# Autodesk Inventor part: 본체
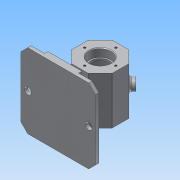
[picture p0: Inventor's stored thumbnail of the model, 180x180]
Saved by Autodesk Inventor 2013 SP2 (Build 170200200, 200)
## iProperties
Created: 2018-06
Part Number: 본체
Material: 알루미늄 6061
Document SubType Name: Modeling
Designer: Administrator
Density: 2.71 g/cm^3
Mass: 554.05 g
Surface Area: 601.88 cm^2
Volume: 204.446 cm^3
Author: Administrator
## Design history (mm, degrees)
sketch "스케치1"
  geometry: L1 (-55, -57)-(55, -57); L2 (55, -57)-(55, -62); L3 (55, -62)-(-55, -62); L4 (-55, -62)-(-55, -57); L5 (12.426, 30)-(30, 12.426); L6 (30, 12.426)-(30, -12.426); L7 (30, -12.426)-(12.426, -30); L8 (12.426, -30)-(-12.426, -30); L9 (-12.426, -30)-(-30, -12.426); L10 (-30, -12.426)-(-30, 12.426); L11 (-30, 12.426)-(-12.426, 30); L12 (-12.426, 30)-(12.426, 30); L13 (0, 0)-(-12.426, 30); L14 (0, 0)-(12.426, 30); L15 (-25, -57)-(25, -57); L16 (25, -57)-(25, -52); L17 (25, -52)-(-25, -52); L18 (-25, -52)-(-25, -57); C1 r 30 at (0, 0); 4 further points
  constraints: 36 end point, 4 parallel, 3 midpoint, 2 horizontal, 2 perpendicular, 2 vertical alignment, 1 centre point, 1 coincident, 1 horizontal alignment, 1 point on line, 1 tangent, 17 other
  dimensions: "d14" = 60 diameter of C1; "d16" = 110 distance of L2.end L3.end; "d17" = 5 distance of L3.end L1.start; "d18" = 62 distance from line of point (0, 0) L3; "d20" = 60 distance between parallel lines of L6 L10; "d21" = 30 vertical distance of L13.start L11.end; "d24" = 5 distance of L17.end L15.start; "d25" = 50 distance of L16.end L17.end
extrude "돌출1" new body sketch "스케치1" stored distance "d22" = 70; taper "d23" = 0 deg
extrude "돌출2" join sketch "스케치1" stored distance "d26" = 110; taper "d27" = 0 deg
extrude "돌출3" join sketch "스케치1" stored distance "d28" = 110; taper "d29" = 0 deg
sketch "스케치2"
  geometry: L1 (0, 110)-(50, 110) reference; L2 (20, 74)-(20, 36); L3 (30, 36)-(30, 74); A1 r 5 centre (25, 36) between (20, 36) and (30, 36); A2 r 5 centre (25, 74) between (30, 74) and (20, 74); 2 further points
  constraints: 4 end point, 4 point on circle, 4 tangent, 2 centre point, 1 horizontal alignment, 1 midpoint, 1 parallel, 1 perpendicular, 1 vertical alignment
  dimensions: "d30" = 38 distance of A2.centre A1.centre; "d32" = 5 radius of A2
extrude "돌출4" join sketch "스케치2" stored distance "d33" = 110; taper "d34" = 0 deg
sketch "스케치3"
  geometry: 2 further points
  constraints: 1 vertical alignment
  dimensions: "d35" = 23 distance of point (0, 0) point (0, 23)
hole "구멍1" sketch "스케치3" at (0, 23) diameter "d36" = 3.242; stored, may be unused: countersink angle "d40" = 90 deg, drill point angle "d42" = 118 deg; dims "d37" = 8, "d38" = 4, "d39" = 2, "d41" = 10
sketch "스케치4"
  geometry: 1 further point
hole "구멍2" sketch "스케치4" at (0, 0) diameter "d46" = 28; stored, may be unused: countersink angle "d50" = 90 deg, drill point angle "d52" = 0 deg; dims "d47" = 8, "d48" = 32, "d49" = 12, "d51" = 15
hole "구멍3" diameter "d55" = 50; stored, may be unused: countersink angle "d59" = 90 deg, drill point angle "d61" = 0 deg; dims "d53" = 10, "d54" = 10, "d56" = 8, "d57" = 32, "d58" = 12, "d60" = 40
sketch "스케치5"
  geometry: L1 (0, 0)-(26.163, 26.163); L2 (0, 0)-(37, 0)
  constraints: 4 end point, 1 equal length, 1 horizontal
  dimensions: "d62" = 37 distance of L1.start L1.end; "d63" = 45 deg angle of L2 L1
node "작업 평면1"
sketch "스케치6"
  geometry: C1 r 8 at (0, 0); 1 further point
  constraints: 1 centre point, 1 coincident
  dimensions: "d64" = 16 diameter of C1
extrude "돌출5" join sketch "스케치6" stored distance "d66" = 110; taper "d67" = 0 deg
hole "구멍4" diameter "d70" = 8; stored, may be unused: countersink angle "d74" = 90 deg, drill point angle "d76" = 0 deg; dims "d68" = 10, "d69" = 10, "d71" = 8, "d72" = 32, "d73" = 12, "d75" = 40
sketch "스케치7"
  geometry: L1 (0, 110)-(0, 0) reference; C1 r 5 at (-10, 55); 2 further points
  constraints: 1 centre point, 1 horizontal alignment, 1 midpoint
  dimensions: "d77" = 10 diameter of C1; "d79" = 10 distance from line of L1 C1.centre
extrude "돌출6" cut sketch "스케치7" stored distance "d80" = 110; taper "d81" = 0 deg
sketch "스케치8"
  geometry: L1 (24.853, 0)-(0, 0) reference; L2 (-17.574, 0)-(-17.574, 70) reference; 2 further points
  constraints: 1 other
  dimensions: "d82" = 35 distance from line of L1 point (12.426, 35); "d83" = 30 distance from line of L2 point (12.426, 35)
feature "엠보싱1" sketch "스케치8" dims "d16" = 110, "d17" = 5, "d18" = 62, "d24" = 5, "d25" = 50, "d84" = 0.5, "d85" = 0
chamfer "모따기1" distance "d86" = 10; stored, may be unused: second distance "d87" = 2, angle "d88" = 45 deg
chamfer "모따기2" distance "d89" = 1; stored, may be unused: second distance "d90" = 2, angle "d91" = 45 deg
fillet "모깎기1" dims "d92" = 0.3, "d93" = 3, "d94" = 1, "d95" = 2
node "솔리드1"
pattern_circular "원형 패턴1" dims angle "d44" = 360 deg
mirror "대칭1"
mirror "대칭2"
